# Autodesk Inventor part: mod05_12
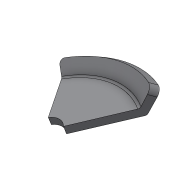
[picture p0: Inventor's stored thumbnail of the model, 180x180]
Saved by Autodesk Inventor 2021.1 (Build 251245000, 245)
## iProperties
Created: 2001-06
Part Number: mod05_12
Document SubType Name: Modeling
Designer: rak
Density: 1 g/cm^3
Material: Generic
Appearance: Default
Control State: 0
Master: False
Checked Out: False
Length Units: 11269
Angle Units: 11279
Time Units: 11290
Mass Units: 11283
Shininess: 3
Angle Display Precision: 2
Document Length Units: 11269
Document Angle Units: 11279
Document Time Units: 11290
Document Mass Units: 11283
Document Length Units Precision: 3
Document Angle Units Precision: 2
Density: 0.0
Volumn: 0.0
Area: 0.0
PropertySet Name: Model Information
Author: rak
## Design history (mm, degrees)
sketch "Sketch2"
  geometry: L1 (-24.906, 26.922)-(15.094, 26.922); L2 (15.094, 26.922)-(23.17, 14.281); L3 (23.17, 14.281)-(18.957, 11.589); L4 (18.957, 11.589)-(12.355, 21.922); L5 (12.355, 21.922)-(-24.906, 21.922); L6 (-24.906, 21.922)-(-24.906, 26.922); L7 (-34.906, 36.669)-(-34.906, 8.293)
  constraints: 14 end point, 3 perpendicular, 2 parallel, 1 horizontal
  dimensions: "d0" = 10 distance between parallel lines of L6 L7; "d1" = 5 distance of L2.end L3.end; "d2" = 5 distance of L5.end L1.start (= d1); "d3" = 40 distance of L1.start L1.end; "d4" = 15 distance of L1.end L2.end
revolve "Revolution1" sketch "Sketch2" stored, may be unused: angle "d5" = 80 deg
fillet "Fillet1" dims "d6" = 4, "d7" = 2
body "Solid1"
